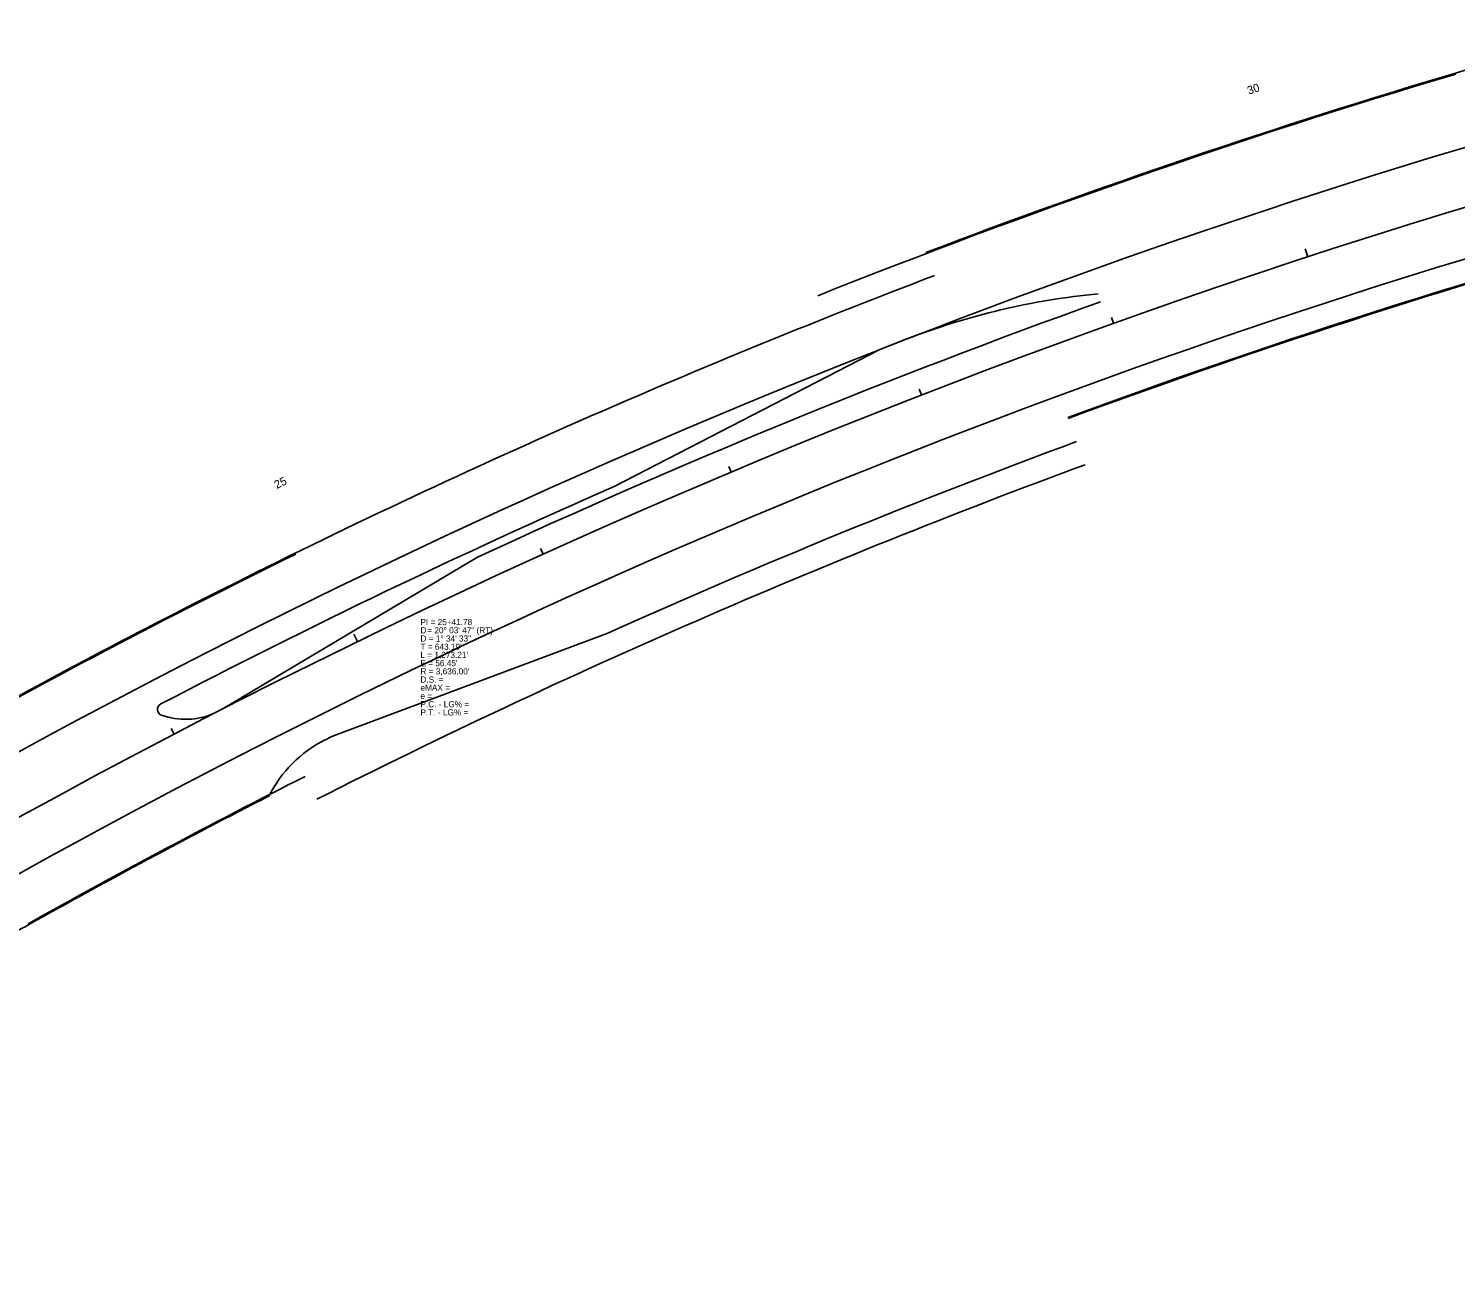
# Model space of a CAD drawing. Extents: x 2004390 to 2007638, y 1136392 to 1138193.
# Drawn here: x 2004747 to 2005442, y 1136432 to 1137038 of the extents above; entities that cross this region are included whole.
import ezdxf

# ---------------------------------------------------------------- set-up
doc = ezdxf.new("R2010")
doc.units = 0
for name, color, linetype in [('RD_HC_Cl', 7, 'Continuous'), ('RD_HC_Data', 7, 'Continuous'), ('RD_HC_Data_Tic', 7, 'Continuous'), ('RD_HC_TX_Sta20', 7, 'Continuous'), ('RD_PD_ConcMed', 7, 'Continuous'), ('RD_PD_Final_TrvlWay', 7, 'Continuous'), ('RD_PD_SideStreet', 7, 'Continuous'), ('RD_PD_SW', 7, 'Continuous')]:
    doc.layers.add(name, color=color, linetype=linetype)

msp = doc.modelspace()

# ---------------------------------------------------------------- linework, layer by layer
at = {"layer": 'RD_HC_Cl'}
msp.add_arc((2006499.76, 1133470.27), 3636, 105.38893, 125.45202, dxfattribs=at)
at = {"layer": 'RD_HC_Data_Tic'}
for p, q in [((2005370.37, 1136926.42), (2005369.13, 1136930.23)), ((2005275.76, 1136894.06), (2005274.75, 1136896.89)), ((2005182.07, 1136859.11), (2005180.98, 1136861.9)), ((2005089.38, 1136821.59), (2005088.21, 1136824.35)), ((2004997.75, 1136781.54), (2004996.51, 1136784.27)), ((2004907.26, 1136738.98), (2004905.51, 1136742.58)), ((2004817.98, 1136693.95), (2004816.59, 1136696.61))]:
    msp.add_line(p, q, dxfattribs=at)
at = {"layer": 'RD_PD_ConcMed'}
for p, q in [((2005032.71, 1136814.65), (2005161.9, 1136881.29)), ((2004841.36, 1136706.04), (2004965.73, 1136780.05))]:
    msp.add_line(p, q, dxfattribs=at)
for centre, radius, start, end in [((2006499.76, 1133470.27), 3648, 109.71047, 114.86698), ((2005301.17, 1136559.93), 350, 95.39245, 111.20302), ((2006499.76, 1133470.27), 3664, 111.20302, 111.416), ((2006499.76, 1133470.27), 3652, 113.68514, 117.53543), ((2004812.84, 1136705.93), 3, 117.53543, 250.61492), ((2004823.46, 1136736.12), 35, 250.61492, 293.58284)]:
    msp.add_arc(centre, radius, start, end, dxfattribs=at)
at = {"layer": 'RD_PD_Final_TrvlWay'}
msp.add_line((2004895.57, 1136693.1), (2005029.35, 1136743.14), dxfattribs=at)
for centre, radius, start, end in [((2006499.76, 1133470.27), 3700, 105.38893, 106.60652), ((2006499.76, 1133470.27), 3700, 106.60652, 110.82775), ((2006499.76, 1133470.27), 3664, 105.38893, 119.73334), ((2006499.76, 1133470.27), 3612, 105.38893, 119.73334), ((2006499.76, 1133470.27), 3600, 105.3281, 110.25357), ((2006499.76, 1133470.27), 3688, 110.82775, 116.80595), ((2006499.76, 1133470.27), 3588, 110.25357, 114.19305), ((2006499.76, 1133470.27), 3688, 116.80595, 119.33961), ((2004918.13, 1136637.3), 60, 116.53783, 153.69809), ((2006499.76, 1133470.27), 3600, 116.46219, 116.53783), ((2006499.76, 1133470.27), 3588, 117.11659, 119.24177), ((2006499.76, 1133470.27), 3588, 119.24177, 119.73334)]:
    msp.add_arc(centre, radius, start, end, dxfattribs=at)
at = {"layer": 'RD_PD_SideStreet'}
for radius, start, end in [(3699.5, 106.60652, 111.70558), (3600.5, 105.38893, 110.25357), (3687.5, 116.10396, 119.33961), (3588.5, 116.79982, 119.24177)]:
    msp.add_arc((2006499.76, 1133470.27), radius, start, end, dxfattribs=at)
at = {"layer": 'RD_PD_SW'}
msp.add_arc((2006499.76, 1133470.27), 3576, 110.25357, 116.79982, dxfattribs=at)

# ---------------------------------------------------------------- texts
at = {"layer": 'RD_HC_Data'}
for s, p in [('PI = 25+41.78', (2004938, 1136747)), ('D', (2004938, 1136743)), ('   = 20%%d 03\' 47" (RT)', (2004938, 1136743)), ("T = 643.19'", (2004938, 1136735)), ('D = 1%%d 34\' 33"', (2004938, 1136739)), ("L = 1,273.21'", (2004938, 1136731)), ("E = 56.45'", (2004938, 1136727)), ("R = 3,636.00'", (2004938, 1136723)), ('eMAX = ', (2004938, 1136715)), ('D.S. = ', (2004938, 1136719)), ('e = ', (2004938, 1136711)), ('P.C. - LG% = ', (2004938, 1136707)), ('P.T. - LG% = ', (2004938, 1136703))]:
    msp.add_text(s, height=3, dxfattribs=at).set_placement(p)
at = {"layer": 'RD_HC_TX_Sta20'}
for s, rotation, p in [('30', 18.09612, (2005341.61, 1137005.4)), ('25', 25.97508, (2004867.96, 1136813.27))]:
    msp.add_text(s, height=4, rotation=rotation, dxfattribs=at).set_placement(p)

doc.saveas('drawing.dxf')
